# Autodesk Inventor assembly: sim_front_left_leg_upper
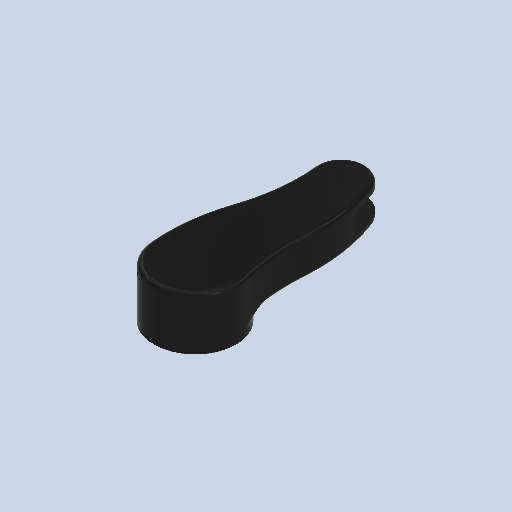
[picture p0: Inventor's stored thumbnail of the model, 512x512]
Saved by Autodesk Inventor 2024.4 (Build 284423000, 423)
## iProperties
Created: 2026-01
Part Number: sim_front_left_leg_upper
Document SubType Name: Assembly
Designer: AdminForWorker
Title: hind_left_leg_upper v2
Author: AdminForWorker
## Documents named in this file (3)
- c:\worker\convert-fusion-r06-cosv3\tmp\job-1\17\temp\files\d3ccd461-8294-4559-92be-f6f526c75b19\5b4bee35-7523-4a42-814c-b3b6f70ad359.iam
- c:\worker\convert-fusion-r06-cosv3\tmp\job-1\17\temp\files\d3ccd461-8294-4559-92be-f6f526c75b19\leg_upper_inner.ipt
- c:\worker\convert-fusion-r06-cosv3\tmp\job-1\17\temp\files\d3ccd461-8294-4559-92be-f6f526c75b19\leg_upper_outer.ipt
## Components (2 placed, 2 different names)
1. leg_upper_inner:1
2. leg_upper_outer:1
